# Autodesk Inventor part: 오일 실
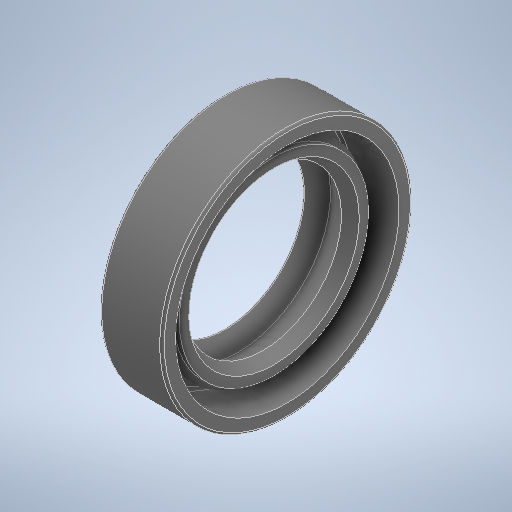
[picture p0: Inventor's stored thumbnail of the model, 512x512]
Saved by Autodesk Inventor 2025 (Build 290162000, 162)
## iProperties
Created: 2024-08
Part Number: 오일 실
Material: 고무
Description: 오일-실
Document SubType Name: Modeling
Designer: onair
Density: 0.93 g/cm^3
Appearance: 기본값
Author: jhkim
Sending System: Autodesk Inventor 2025
Preprocessor: ST-DEVELOPER v20
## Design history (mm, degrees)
feature "Solid1"
node "솔리드1"
